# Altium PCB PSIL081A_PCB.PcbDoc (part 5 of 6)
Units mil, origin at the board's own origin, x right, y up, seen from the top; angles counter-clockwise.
Board outline 14000 x 8000 mil, 10 copper layers (Top Layer, Signal Layer 1, Signal Layer 2, Signal Layer 3, Signal Layer 4, Signal Layer 5, Signal Layer 6, Signal Layer 7, Signal Layer 8, Bottom Layer), stack 60.9 mil thick; 433 components, 510 nets, 1716 pads, 590 vias.
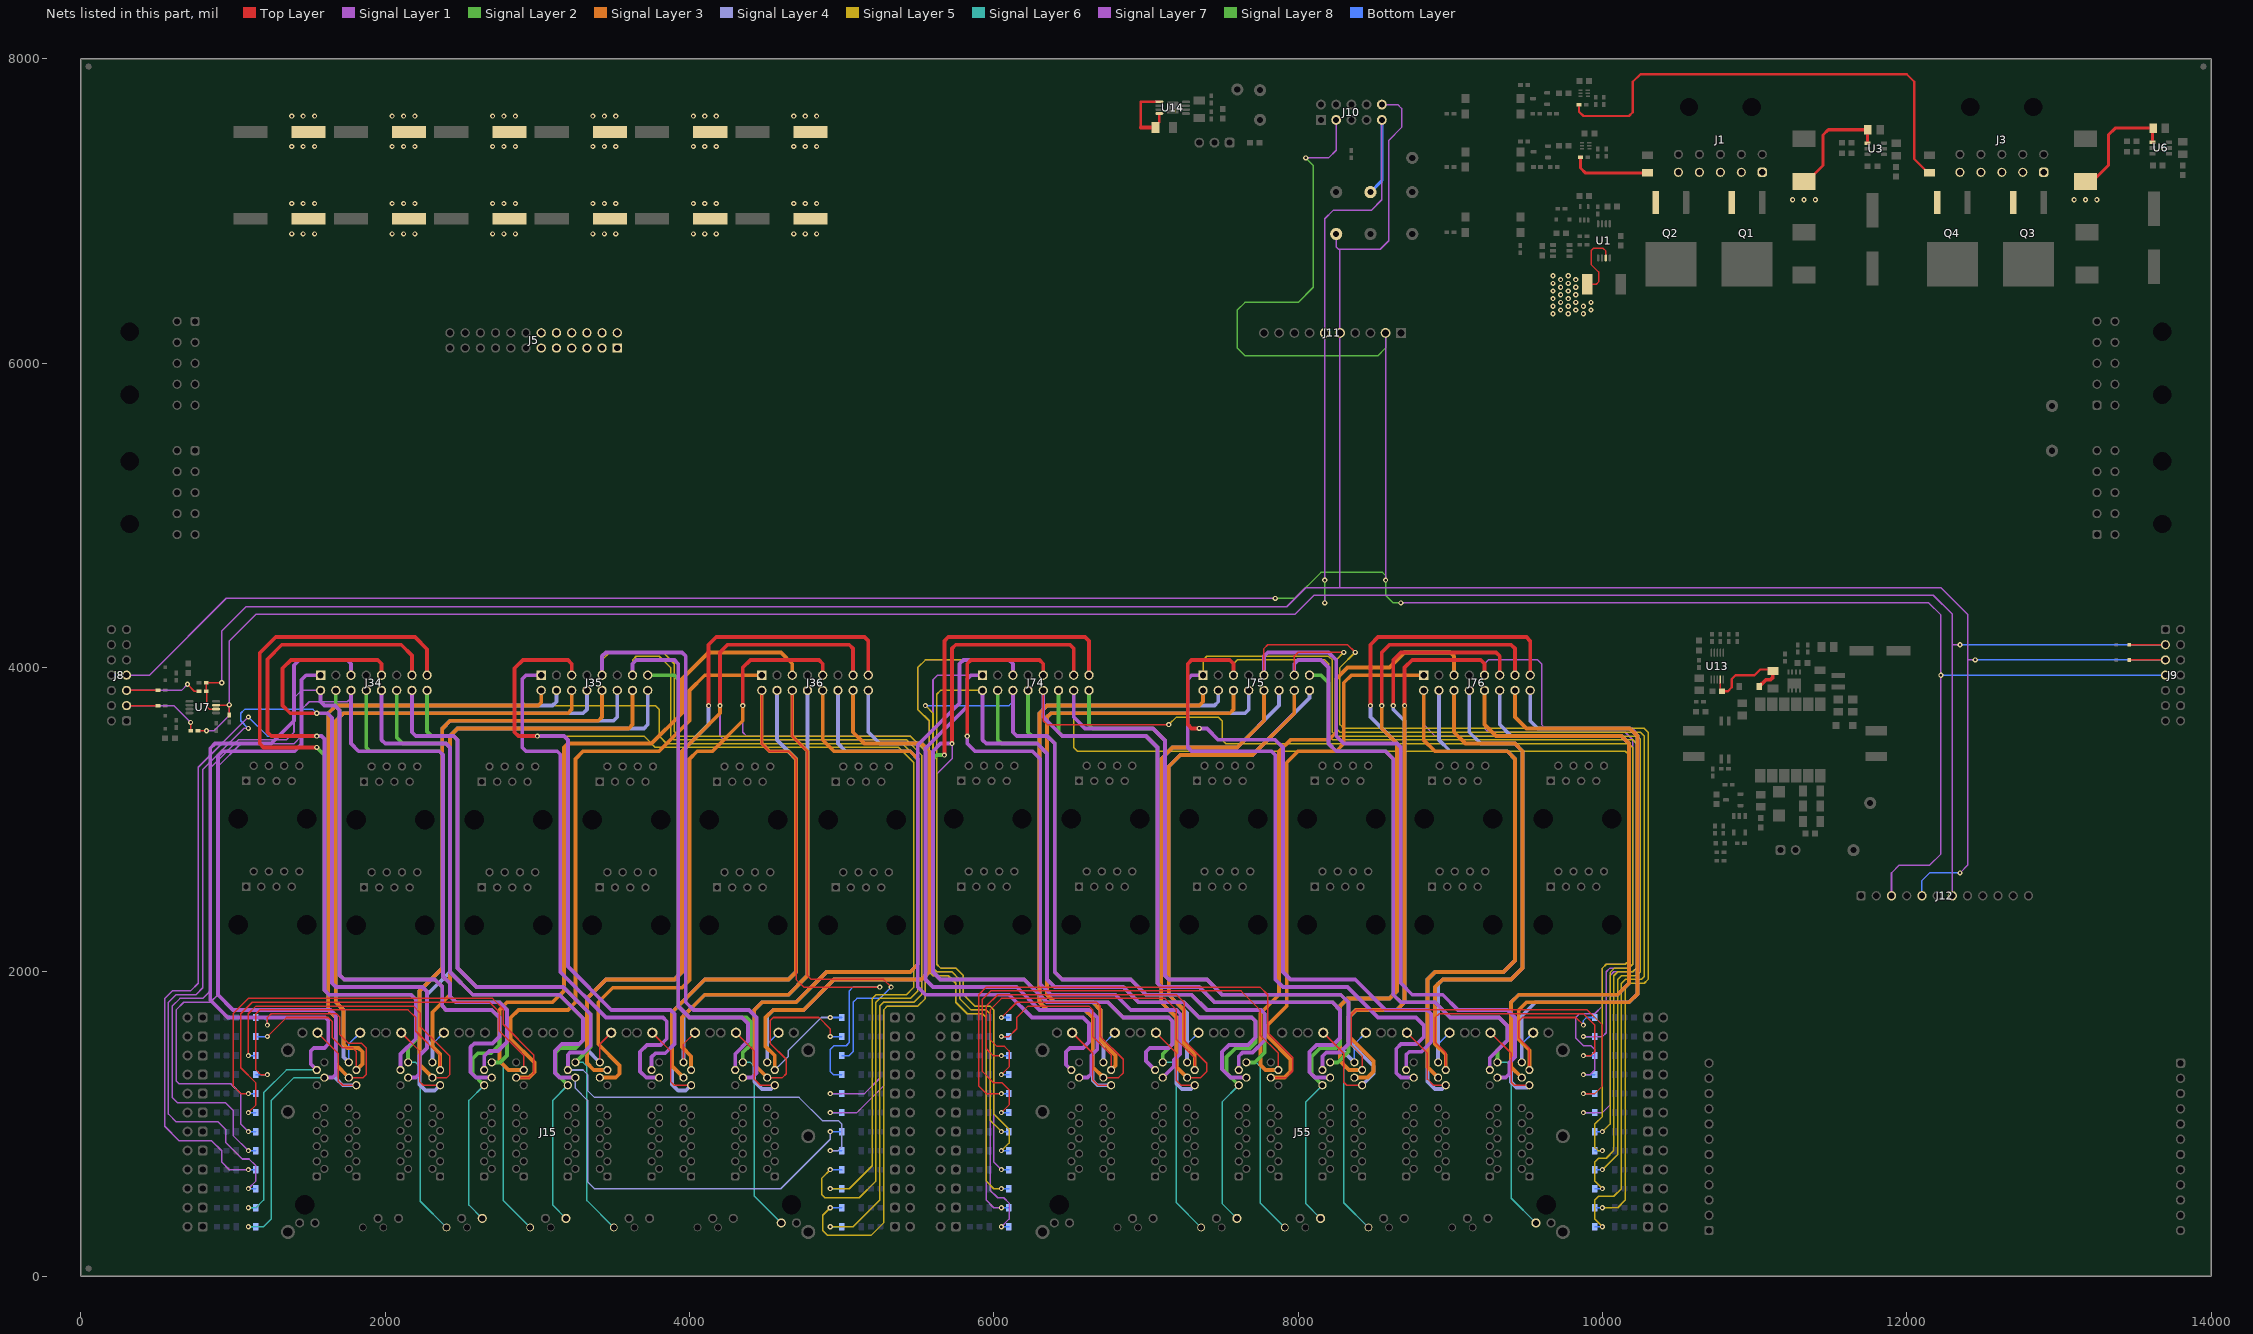
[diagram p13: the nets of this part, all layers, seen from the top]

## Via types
v1: diameter 34, hole 16, Top Layer to Bottom Layer, 429 vias
v2: diameter 26, hole 8, Top Layer to Bottom Layer, 156 vias
v3: diameter 19.68, hole 7.87, Top Layer to Bottom Layer, 5 vias

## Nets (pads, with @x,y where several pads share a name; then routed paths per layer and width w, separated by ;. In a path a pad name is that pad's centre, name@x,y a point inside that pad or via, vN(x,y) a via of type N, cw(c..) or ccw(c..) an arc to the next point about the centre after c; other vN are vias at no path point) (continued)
PSE_N3_F: J55.H11 J55.H16 J76.11 | length 4659.6
  Top Layer w10: J55.H16@8165.04,1599.84 8300,1464.88 8300,1275 8320,1255 8420.12,1255 J55.H11@8420.16,1254.96 ; J55.H11@8409.55,1244.35 8413.94,1239.96 8435.16,1239.96 J55.H11@8435.16,1269.96
  Top Layer w25: v1(8625,3750) 8625,4050 8675,4100 9300,4100 9325,4075 J76.11@9325,3950
  Signal Layer 4 w25: J55.H11@8420.16,1254.96 8495,1329.8 8495,1380 8330,1545 8330,1700 8380,1750 8650,1750 8700,1800 8700,3650 8625,3725 v1(8625,3750)
PSE_N4_A: J15.C14 J15.C17 J34.15 | length 6222.3
  Top Layer w25: v1(1550,3475) 1200,3475 1175,3500 1175,4095 1280,4200 2195,4200 2275,4120 J34.15@2275,3950
  Signal Layer 2 w25: v1(1550,3475) 1600,3425 1600,1880 1630,1850 2170,1850 2200,1820 2200,1550 2149.92,1499.92 J15.C14@2149.92,1404.96
  Signal Layer 6 w10: J15.C14@2149.92,1404.96 2199.96,1404.96 2200,1405 2230,1375 2230,492.21 J15.C17@2402.28,319.92
PSE_N4_B: J15.K14 J15.K17 J35.15 | length 4356.8
  Signal Layer 2 w25: J35.15@3725,3950 3900,3950 3925,3925 3925,1775 4000,1700 4375,1700 4400,1675 4400,1520 4349.92,1469.92 J15.K14@4349.92,1404.96
  Signal Layer 6 w10: J15.K14@4349.92,1404.96 4399.96,1404.96 4400,1405 4425,1380 4425,527.52 J15.K17@4602.68,349.84
PSE_N4_C: J15.H14 J15.H17 J36.15 | length 4907.4
  Top Layer w10: J15.H14@3410.16,1404.96 3410,1405.12 3410,1524.88 J15.H17@3484.96,1599.84
  Top Layer w25: v1(4125,3750) 4125,4150 4175,4200 5150,4200 5175,4175 J36.15@5175,3950
  Signal Layer 4 w25: J15.H14@3410.16,1404.96 3325,1490.12 3325,1825 3450,1950 3900,1950 3950,2000 3950,3450 4125,3625 v1(4125,3750)
PSE_N4_D: J55.C14 J55.C17 J74.15 | length 6665.4
  Top Layer w25: v1(5675,3425) 5675,4175 5700,4200 6600,4200 6625,4175 J74.15@6625,3950
  Signal Layer 2 w25: v1(5675,3425) 5625,3425 5600,3400 5600,2000 5650,1950 6200,1950 6350,1800 6750,1800 6850,1700 7150,1700 7175,1675 7175,1525 7109.92,1459.92 J55.C14@7109.92,1404.96
  Signal Layer 6 w10: J55.C14@7109.92,1404.96 7174.96,1404.96 7175,1405 7200,1380 7200,482.2 J55.C17@7362.28,319.92
PSE_N4_E: J55.K14 J55.K17 J75.15 | length 4862
  Signal Layer 2 w25: J75.15@8075,3950 8150,3950 8200,3900 8200,3500 8250,3450 8575,3450 8625,3400 8625,1850 8675,1800 8900,1800 9000,1700 9320,1700 9375,1645 9375,1550 9309.92,1484.92 J55.K14@9309.92,1404.96
  Signal Layer 6 w10: J55.K14@9309.92,1404.96 9309.96,1405 9375,1405 9400,1380 9400,512.52 J55.K17@9562.68,349.84
PSE_N4_F: J55.H14 J55.H17 J76.15 | length 4705.3
  Top Layer w25: v1(8475,3750) 8475,4150 8525,4200 9500,4200 9525,4175 J76.15@9525,3950
  Signal Layer 4 w25: J55.H14@8370.16,1404.96 8275,1500.12 8275,1775 8325,1825 8600,1825 8650,1875 8650,3500 8475,3675 v1(8475,3750)
  Bottom Layer w10: J55.H14@8370.16,1404.96 8370.16,1525.04 J55.H17@8444.96,1599.84
PSE_N5_A: J15.E11 J15.E16 J34.4 | length 4670.7
  Signal Layer 2 w25: J34.4@1675,3850 1675,3745 1700,3720 1700,1980 1730,1950 2325,1950 2375,1900 2375,1775 2400,1750 2700,1750 2750,1700 2750,1520 2695,1465 2610,1465 2575,1430 2575,1329.88 J15.E11@2649.92,1254.96
  Signal Layer 6 w10: J15.E16@2637.32,379.76 2550,467.09 2550,1155.04 J15.E11@2649.92,1254.96
PSE_N5_B: J15.B11 J15.B16 J35.4 | length 4683.9
  Top Layer w10: J15.B16@1555.04,1599.84 1690,1464.88 1690,1285 1720,1255 1810.12,1255 J15.B11@1810.16,1254.96
  Signal Layer 4 w25: J15.B11@1810.16,1254.96 1810.12,1255 1720,1255 1675,1300 1675,1700 1625,1750 1625,3700 1675,3750 3100,3750 3125,3775 J35.4@3125,3850
PSE_N5_C: J15.J11 J15.J16 J36.4 | length 3972.8
  Top Layer w10: J15.J16@3755.04,1599.84 3875,1479.88 3875,1280 3900,1255 4010.12,1255 J15.J11@4010.16,1254.96
  Signal Layer 4 w25: J15.J11@4010.16,1254.96 3975.2,1220 3925,1220 3885,1260 3885,1735 4100,1950 4650,1950 4700,2000 4700,3400 4575,3525 J36.4@4575,3850
PSE_N5_D: J55.E11 J55.E16 J74.4 | length 5204.7
  Signal Layer 2 w25: J74.4@6025,3850 6025,3525 6050,3500 6285,3500 6350,3435 6350,1950 6400,1900 6850,1900 6950,1800 7250,1800 7350,1700 7695,1700 7720,1675 7720,1535 7685,1500 7590,1500 7530,1440 7530,1334.88 J55.E11@7609.92,1254.96
  Signal Layer 6 w10: J55.E16@7597.32,379.76 7500,477.09 7500,1145.04 J55.E11@7609.92,1254.96
PSE_N5_E: J55.B11 J55.B16 J75.4 | length 4620.5
  Top Layer w10: J55.B16@6515.04,1599.84 6650,1464.88 6650,1290 6685,1255 6770.12,1255 J55.B11@6770.16,1254.96
  Signal Layer 4 w25: J55.B11@6770.16,1254.96 6770.12,1255 6680,1255 6650,1285 6650,1700 6600,1750 6350,1750 6300,1800 6300,3700 6350,3750 7450,3750 7475,3775 J75.4@7475,3850
PSE_N5_F: J55.J11 J55.J16 J76.4 | length 4147.2
  Top Layer w10: J55.J16@8715.04,1599.84 8850,1464.88 8850,1295 8890,1255 8970.12,1255 J55.J11@8970.16,1254.96
  Signal Layer 4 w25: J76.4@8925,3850 8925,3525 9000,3450 9375,3450 9425,3400 9425,2075 9350,2000 8900,2000 8850,1950 8850,1280 8900,1230 8945.2,1230 J55.J11@8970.16,1254.96
PSE_N6_A: J15.E14 J15.E17 J34.8 | length 4554.3
  Signal Layer 2 w25: J34.8@1875,3850 1875,3475 1900,3450 2355,3450 2380,3425 2380,1970 2425,1925 2425,1840 2465,1800 2750,1800 2800,1750 2800,1450 2754.96,1404.96 J15.E14@2699.92,1404.96
  Signal Layer 6 w10: J15.E14@2699.92,1404.96 2749.96,1404.96 2750,1405 2775,1380 2775,497.21 J15.E17@2952.28,319.92
PSE_N6_B: J15.B14 J15.B17 J35.8 | length 4312.2
  Signal Layer 4 w25: J15.B14@1760.16,1404.96 1725,1440.12 1725,1750 1675,1800 1675,3650 1725,3700 3300,3700 3325,3725 J35.8@3325,3850
  Bottom Layer w10: J15.B14@1760.16,1404.96 1760.16,1525.04 J15.B17@1834.96,1599.84
PSE_N6_C: J15.J14 J15.J17 J36.8 | length 3345
  Top Layer w10: J15.J14@3960.16,1404.96 3960.16,1525.04 J15.J17@4034.96,1599.84
  Signal Layer 4 w25: J15.J14@3950,1405 J15.J14@3960.16,1394.84 ; J15.J14@3960.16,1404.96 3960.16,1710.16 4100,1850 4650,1850 4775,1975 J36.8@4775,3850
PSE_N6_D: J55.E14 J55.E17 J74.8 | length 5104.7
  Signal Layer 2 w25: J74.8@6225,3850 6225,3575 6250,3550 6350,3550 6400,3500 6400,2000 6450,1950 6900,1950 7000,1850 7300,1850 7400,1750 7755,1750 7780,1725 7780,1470 7714.96,1404.96 J55.E14@7659.92,1404.96
  Signal Layer 6 w10: J55.E14@7659.92,1404.96 7724.96,1404.96 7725,1405 7750,1380 7750,482.2 J55.E17@7912.28,319.92
PSE_N6_E: J55.B14 J55.B17 J75.8 | length 4266.4
  Signal Layer 4 w25: J55.B14@6720.16,1404.96 6720.16,1529.84 6700,1550 6700,1750 6650,1800 6400,1800 6350,1850 6350,3675 6375,3700 7650,3700 7675,3725 J75.8@7675,3850
  Bottom Layer w10: J55.B14@6720.16,1404.96 6720.16,1525.04 J55.B17@6794.96,1599.84
PSE_N6_F: J55.J14 J55.J17 J76.8 | length 3451.1
  Signal Layer 4 w25: J55.J14@8920.16,1414.84 J55.J14@8920.16,1404.96 8920,1920 8950,1950 9400,1950 9475,2025 9475,3450 9425,3500 9200,3500 9125,3575 J76.8@9125,3850
  Bottom Layer w10: J55.J14@8920.16,1404.96 8920.16,1525.04 J55.J17@8994.96,1599.84
PSE_N7_A: J15.G11 J15.G16 J34.12 | length 4722.3
  Signal Layer 2 w25: J34.12@2075,3850 2075,3540 2115,3500 2400,3500 2425,3475 2425,2000 2575,1850 3145,1850 3300,1695 3300,1550 3250,1500 3150,1500 3120,1470 3120,1334.88 J15.G11@3199.92,1254.96
  Signal Layer 6 w10: J15.G16@3187.32,379.76 3100,467.09 3100,1155.04 J15.G11@3199.92,1254.96
PSE_N7_B: J15.D11 J15.D16 J35.12 | length 4439.5
  Top Layer w10: J15.D16@2105.04,1599.84 2225,1479.88 2225,1280 2250.04,1254.96 J15.D11@2360.16,1254.96 J15.D11@2360.16,1254.96
  Signal Layer 4 w25: J15.D11@2360.16,1254.96 2325.2,1220 2265,1220 2225,1260 2225,1875 2375,2025 2375,3600 2425,3650 3500,3650 3525,3675 J35.12@3525,3850
PSE_N7_C: J15.L11 J15.L16 J36.12 | length 4608.2
  Top Layer w10: J15.L16@4305.04,1599.84 4425,1479.88 4425,1295 4465,1255 4560.12,1255 J15.L11@4560.16,1254.96
  Signal Layer 4 w25: J15.L11@4560.16,1254.96 4535.2,1230 4475,1230 4425,1280 4425,1750 4475,1800 4700,1800 4900,2000 5450,2000 5500,2050 5500,3400 5450,3450 5025,3450 4975,3500 J36.12@4975,3850
PSE_N7_D: J55.G11 J55.G16 J74.12 | length 5412.1
  Signal Layer 2 w25: J74.12@6425,3850 6425,3575 6450,3550 7000,3550 7075,3475 7075,1925 7100,1900 7350,1900 7450,1800 8225,1800 8275,1750 8275,1525 8250,1500 8145,1500 8090,1445 8090,1324.88 J55.G11@8159.92,1254.96
  Signal Layer 6 w10: J55.G16@8147.32,379.76 8050,477.09 8050,1145.04 J55.G11@8159.92,1254.96
PSE_N7_E: J55.D11 J55.D16 J75.12 | length 3844.8
  Top Layer w10: J55.D16@7065.04,1599.84 7200,1464.88 7200,1285 7230,1255 7320.12,1255 J55.D11@7320.16,1254.96 J55.D11@7320.16,1254.96
  Signal Layer 4 w25: J55.D11@7320.16,1254.96 7295.2,1230 7235,1230 7200,1265 7200,1700 7100,1800 7100,3400 7175,3475 7600,3475 7875,3750 J75.12@7875,3850
PSE_N7_F: J55.L11 J55.L16 J76.12 | length 4703.6
  Top Layer w10: J55.L16@9265.04,1599.84 9400,1464.88 9400,1275 9420,1255 9520.12,1255 J55.L11@9520.16,1254.96
  Signal Layer 4 w25: J76.12@9325,3850 9325,3625 9400,3550 10125,3550 10175,3500 10175,1925 10100,1850 9450,1850 9400,1800 9400,1275 9435,1240 9505.2,1240 J55.L11@9520.16,1254.96
PSE_N8_A: J15.G14 J15.G17 J34.16 | length 4569.6
  Signal Layer 2 w25: J34.16@2275,3850 2275,3580 2305,3550 2450,3550 2475,3525 2475,2025 2600,1900 3170,1900 3350,1720 3350,1505.04 J15.G14@3249.92,1404.96
  Signal Layer 6 w10: J15.G14@3249.92,1404.96 3299.96,1404.96 3300,1405 3325,1380 3325,497.21 J15.G17@3502.28,319.92
PSE_N8_B: J15.D14 J15.D17 J35.16 | length 4003.7
  Signal Layer 4 w25: J15.D14@2310.16,1404.96 2310.16,1514.84 2275,1550 2275,1850 2425,2000 2425,3550 2475,3600 3700,3600 3725,3625 J35.16@3725,3850
  Bottom Layer w10: J15.D14@2310.16,1404.96 2310.16,1525.04 J15.D17@2384.96,1599.84
PSE_N8_C: J15.L14 J15.L17 J36.16 | length 3892.7
  Signal Layer 4 w25: J15.L14@4510.16,1404.96 4510.16,1710.16 4550,1750 4750,1750 4950,1950 5525,1950 5575,2000 5575,3450 5525,3500 5250,3500 5175,3575 J36.16@5175,3850
  Bottom Layer w10: J15.L14@4510.16,1404.96 4510.16,1525.04 J15.L17@4584.96,1599.84
PSE_N8_D: J55.G14 J55.G17 J74.16 | length 5292.8
  Signal Layer 2 w25: J74.16@6625,3850 6625,3625 6650,3600 7045,3600 7125,3520 7125,1975 7150,1950 7400,1950 7500,1850 8280,1850 8330,1800 8330,1475 8259.96,1404.96 J55.G14@8209.92,1404.96
  Signal Layer 6 w10: J55.G14@8209.92,1404.96 8274.96,1404.96 8275,1405 8300,1380 8300,482.2 J55.G17@8462.28,319.92
PSE_N8_E: J55.D14 J55.D17 J75.16 | length 3382.1
  Signal Layer 4 w25: J55.D14@7270.16,1404.96 7270.16,1729.84 7150,1850 7150,3350 7225,3425 7700,3425 8075,3800 J75.16@8075,3850
  Bottom Layer w10: J55.D14@7270.16,1404.96 7270.16,1525.04 J55.D17@7344.96,1599.84
PSE_N8_F: J55.L14 J55.L17 J76.16 | length 3992.5
  Signal Layer 4 w25: J55.L14@9470.16,1404.96 9470.16,1709.84 9470,1710 9560,1800 10175,1800 10230,1855 10230,3550 10180,3600 9575,3600 9525,3650 J76.16@9525,3850
  Bottom Layer w10: J55.L14@9470.16,1404.96 9470.16,1525.04 J55.L17@9544.96,1599.84
PSE_P1_A: D10.1 J15.A12 J34.1 | length 5429.5
  Signal Layer 1 w25: J34.1@1575,3950 1480,3950 1450,3920 1450,3495 1405,3450 930,3450 900,3420 900,1850 1000,1750 1640,1750 1675,1715 1675,1325 1654.96,1304.96 J15.A12@1599.92,1304.96
  Signal Layer 6 w10: v1(1100,325) 1200,325 1250,375 1250,1155 1400,1305 J15.A12@1599.92,1304.96 J15.A12@1599.92,1304.96
  Bottom Layer w10: v1(1100,325) D10.1@1148.94,325
PSE_P1_B: D12.1 J15.I12 J35.1 | length 10536.8
  Signal Layer 1 w25: J35.1@3025,3950 2925,3950 2900,3925 2900,3475 2925,3450 3130,3450 3150,3430 3150,2000 3450,1700 3825,1700 3850,1675 3850,1560 3810,1520 3720,1520 3675,1475 3675,1345 3715,1305 J15.I12@3799.92,1304.96 J15.I12@3799.92,1304.96
  Signal Layer 5 w10: J35.1@3025,3950 2925,3950 2900,3925 2900,3775 2925,3750 3775,3750 3800,3725 3800,3550 3850,3500 5400,3500 5500,3400 5500,1875 5450,1825 5250,1825 5225,1800 5225,625 5115,515 4890,515 4870,535 4870,645 v1(4925,700)
  Bottom Layer w10: v1(4925,700) D12.1@5000.53,700
PSE_P1_C: D17.1 J15.F12 J36.1 | length 7342.6
  Top Layer w10: v1(1100,1200) 1050,1200 1000,1250 1000,1725 1100,1825 2705,1825 2775,1755 2775,1655 2975,1455 2975,1335 2945,1305 2875.16,1305 2875.16,1289.96 2853.94,1289.96 J15.F12@2849.55,1294.35
  Signal Layer 3 w25: J15.F12@2860.16,1304.96 2944.96,1304.96 2980,1340 2980,1405 2825,1560 2825,1700 2875,1750 3200,1750 3250,1800 3250,3400 3300,3450 3800,3450 4000,3650 4000,3850 4100,3950 J36.1@4475,3950
  Bottom Layer w10: v1(1100,1200) D17.1@1148.94,1200
PSE_P1_D: D34.1 J55.A12 J74.1 | length 8260.1
  Signal Layer 1 w25: J74.1@5925,3950 5850,3950 5825,3925 5825,3745 5550,3470 5550,1950 5600,1900 6150,1900 6300,1750 6630,1750 6680,1700 6680,1490 6640,1450 6640,1330 6614.96,1304.96 J55.A12@6559.92,1304.96
  Signal Layer 7 w10: J74.1@5925,3950 5630,3950 5600,3920 5600,2025 5625,2000 5725,2000 5775,1950 5775,1825 5850,1750 5950,1750 5975,1725 5975,565 6025,515 6065,515 6100,480 6100,375 v1(6050,325)
  Bottom Layer w10: v1(6050,325) D34.1@6099.47,325
PSE_P1_E: D36.1 J55.I12 J75.1 | length 10839.7
  Signal Layer 1 w25: J75.1@7375,3950 7300,3950 7275,3925 7275,3475 7300,3450 7825,3450 7850,3425 7850,1950 7900,1900 8325,1900 8525,1700 8775,1700 8825,1650 8825,1570 8780,1525 8675,1525 8645,1495 8645,1335 8675,1305 J55.I12@8759.92,1304.96 J55.I12@8759.92,1304.96
  Signal Layer 5 w10: J75.1@7375,3950 7375,4050 7400,4075 8200,4075 8225,4050 8225,3575 8250,3550 10230,3550 10250,3530 10250,2000 10225,1975 10125,1975 10100,1950 10100,800 v1(10000,700)
  Bottom Layer w10: D36.1@9950.53,700 v1(10000,700)
PSE_P1_F: D41.1 J55.F12 J76.1 | length 7156.4
  Top Layer w10: v1(6050,1200) 5950,1200 5900,1250 5900,1850 5950,1900 7750,1900 7800,1850 7800,1600 7965,1435 7965,1349.8 7920.2,1305 J55.F12@7820.16,1304.96 J55.F12@7820.16,1304.96
  Signal Layer 3 w25: J55.F12@7820.16,1304.96 7909.96,1304.96 7950,1345 7950,1425 7800,1575 7800,1650 7925,1775 7925,3375 8000,3450 8250,3450 8300,3500 8300,3900 8350,3950 J76.1@8825,3950
  Bottom Layer w10: v1(6050,1200) D41.1@6099.47,1200
PSE_P2_A: D13.1 J15.A13 J34.5 | length 5667.3
  Signal Layer 1 w25: J15.A13@1549.92,1354.96 1510,1394.88 1510,1480 1530,1500 1600,1500 1625,1525 1625,1680 1605,1700 965,1700 850,1815 850,3470 880,3500 1250,3500 1400,3650 1400,4015 1435,4050 1750,4050 1775,4025 J34.5@1775,3950
  Signal Layer 6 w10: v1(1100,450) 1150,450 1200,500 1200,1205 1350,1355 J15.A13@1549.92,1354.96 J15.A13@1549.92,1354.96
  Bottom Layer w10: v1(1100,450) D13.1@1148.94,450
PSE_P2_B: D15.1 J15.I13 J35.5 | length 9903.8
  Top Layer w25: v1(3000,3550) 2875,3550 2850,3575 2850,3995 2905,4050 3200,4050 3225,4025 J35.5@3225,3950
  Signal Layer 1 w25: v1(3000,3550) 3175,3550 3200,3525 3200,2035 3485,1750 3875,1750 3900,1725 3900,1525 3840,1465 3775,1465 3750,1440 3750,1355.04 J15.I13@3749.92,1354.96
  Signal Layer 5 w10: v1(3000,3550) 3700,3550 3775,3475 5375,3475 5475,3375 5475,1900 5425,1850 5225,1850 5200,1825 5200,725 5050,575 v1(4925,575)
  Bottom Layer w10: v1(4925,575) D15.1@5000.53,575
PSE_P2_C: D20.1 J15.F13 J36.5 | length 7559
  Top Layer w10: v1(1100,1075) 1150,1125 1150,1270 1050,1370 1050,1725 1125,1800 2685,1800 2750,1735 2750,1610 2910.16,1449.84 J15.F13@2910.16,1354.96
  Signal Layer 3 w25: J15.F13@2910.16,1354.96 2910.12,1355 2810,1355 2750,1415 2750,1750 2800,1800 3100,1800 3175,1875 3175,3475 3200,3500 3750,3500 3950,3700 3950,3925 4125,4100 4600,4100 4675,4025 J36.5@4675,3950
  Bottom Layer w10: v1(1100,1075) D20.1@1148.94,1075
PSE_P2_D: D37.1 J55.A13 J74.5 | length 9045.3
  Signal Layer 1 w25: J74.5@6125,3950 6125,4025 6100,4050 5800,4050 5775,4025 5775,3765 5500,3490 5500,1900 5550,1850 6100,1850 6250,1700 6585,1700 6625,1660 6625,1540 6585,1500 6500,1500 6475,1475 6475,1389.88 J55.A13@6509.92,1354.96
  Signal Layer 7 w10: v1(6050,450) 6000,450 5950,500 5950,1700 5925,1725 5825,1725 5750,1800 5750,1925 5700,1975 5600,1975 5575,2000 5575,3650 5500,3725 5500,4000 5550,4050 6100,4050 6125,4025 J74.5@6125,3950
  Bottom Layer w10: v1(6050,450) D37.1@6099.47,450
PSE_P2_E: D39.1 J55.I13 J75.5 | length 10970.4
  Top Layer w25: v1(7350,3600) 7300,3600 7275,3625 7275,4025 7300,4050 7550,4050 7575,4025 J75.5@7575,3950
  Signal Layer 1 w25: v1(7350,3600) 7400,3600 7475,3525 7850,3525 7900,3475 7900,2000 7950,1950 8375,1950 8575,1750 8850,1750 8875,1725 8875,1540 8810,1475 8730,1475 8710,1455 8710,1355.04 J55.I13@8709.92,1354.96
  Signal Layer 5 w10: J75.5@7575,3950 7575,4025 7600,4050 8175,4050 8200,4025 8200,3550 8225,3525 10200,3525 10225,3500 10225,2025 10200,2000 10100,2000 10075,1975 10075,825 10025,775 9975,775 9950,750 9950,625 v1(10000,575)
  Bottom Layer w10: D39.1@9950.53,575 v1(10000,575)
PSE_P2_F: D44.1 J55.F13 J76.5 | length 7268.2
  Top Layer w10: v1(6050,1075) 6100,1125 6100,1225 6055,1270 6000,1270 5925,1345 5925,1820 5980,1875 7625,1875 7750,1750 7750,1585 7870.16,1464.84 J55.F13@7870.16,1354.96
  Signal Layer 3 w25: J55.F13@7870.16,1354.96 7870.12,1355 7785,1355 7752.5,1387.5 7752.5,1727.5 7875,1850 7875,3450 7950,3525 8200,3525 8250,3575 8250,3925 8325,4000 8600,4000 8700,4100 9000,4100 9025,4075 J76.5@9025,3950
  Bottom Layer w10: v1(6050,1075) D44.1@6099.47,1075
PSE_P3_A: D22.1 J15.C12 J34.9 | length 8873.1
  Top Layer w25: v1(1550,3700) 1375,3700 1325,3750 1325,3995 1380,4050 1950,4050 1975,4025 J34.9@1975,3950
  Signal Layer 1 w25: v1(1550,3700) 1620,3700 1650,3670 1650,1925 1675,1900 2245,1900 2275,1870 2275,1500 2225,1450 2225,1330 2199.96,1304.96 J15.C12@2149.92,1304.96
  Signal Layer 7 w10: v1(1100,575) 1150,625 1150,725 1105,770 1060,770 950,880 950,965 900,1015 625,1015 575,1065 575,1800 625,1850 755,1850 800,1895 800,3330 1070,3600 v1(1100,3600)
  Bottom Layer w10: v1(1100,575) D22.1@1148.94,575 ; v1(1100,3600) 1050,3650 1050,3700 1075,3725 1525,3725 v1(1550,3700)
PSE_P3_B: D24.1 J15.K12 J35.9 | length 10743.1
  Signal Layer 1 w25: J35.9@3425,3950 3425,4075 3450,4100 3950,4100 3975,4075 3975,1800 4025,1750 4390,1750 4440,1700 4440,1335 4409.96,1304.96 J15.K12@4349.92,1304.96
  Signal Layer 5 w10: J35.9@3425,3950 3425,4050 3475,4100 3825,4100 3900,4025 3900,3580 3930,3550 5450,3550 5550,3450 5550,1825 5500,1775 5300,1775 5275,1750 5275,350 5195,270 4905,270 4875,300 4875,400 v1(4925,450)
  Bottom Layer w10: v1(4925,450) D24.1@5000.53,450
PSE_P3_C: D29.1 J15.H12 J36.9 | length 8573.7
  Top Layer w25: v1(4350,3750) 4350,4000 4400,4050 4850,4050 4875,4025 J36.9@4875,3950
  Signal Layer 3 w25: J15.H12@3410.16,1304.96 3514.96,1304.96 3540,1330 3540,1385 3400,1525 3400,1800 3495,1895 3950,1895 4000,1945 4000,3400 4050,3450 4150,3450 4350,3650 v1(4350,3750)
  Signal Layer 7 w10: v1(4350,3750) 4350,3575 4375,3550 5450,3550 5550,3450 5550,1825 5500,1775 5300,1775 5275,1750 5275,1250 5100,1075 v1(4925,1075)
  Bottom Layer w10: v1(4925,1075) D29.1@5000.53,1075
PSE_P3_D: D46.1 J55.C12 J74.9 | length 9370.4
  Top Layer w25: v1(5825,3550) 5825,4025 5850,4050 6300,4050 6325,4025 J74.9@6325,3950
  Signal Layer 1 w25: v1(5825,3550) 5825,3500 5875,3450 6255,3450 6305,3400 6305,1920 6375,1850 6800,1850 6900,1750 7200,1750 7225,1725 7225,1460 7185,1420 7185,1380.04 J55.C12@7109.92,1304.96
  Signal Layer 5 w10: v1(6050,575) 6000,575 5950,625 5950,1700 5925,1725 5825,1725 5750,1800 5750,1925 5700,1975 5600,1975 5575,2000 5575,3650 5500,3725 5500,4000 5550,4050 6300,4050 6325,4025 J74.9@6325,3950
  Bottom Layer w10: v1(6050,575) D46.1@6099.47,575
PSE_P3_E: D48.1 J55.K12 J75.9 | length 11239.4
  Top Layer w10: J75.9@7775,3950 7775,4125 7800,4150 8325,4150 v1(8375,4100)
  Signal Layer 1 w25: J75.9@7775,3950 7775,4075 7800,4100 8200,4100 8250,4050 8250,3550 8300,3500 8650,3500 8675,3475 8675,1925 8750,1850 8950,1850 9050,1750 9375,1750 9425,1700 9425,1440 9390,1405 9390,1330 9364.96,1304.96 J55.K12@9309.92,1304.96
  Signal Layer 5 w10: v1(8375,4100) 8275,4000 8275,3625 8300,3600 10275,3600 10300,3575 10300,1950 10275,1925 10175,1925 10150,1900 10150,500 10100,450 v1(10000,450)
  Bottom Layer w10: D48.1@9950.53,450 v1(10000,450)
PSE_P3_F: D53.1 J55.H12 J76.9 | length 8194.8
  Top Layer w25: v1(8700,3750) 8700,4000 8750,4050 9200,4050 9225,4025 J76.9@9225,3950
  Signal Layer 3 w25: J55.H12@8370.16,1304.96 J55.H12@8370.16,1304.96 8455,1305 8495,1345 8495,1415 8330,1580 8330,1700 8380,1750 8650,1750 8700,1800 v1(8700,3750)
  Signal Layer 7 w10: J76.9@9225,3950 9225,4025 9250,4050 9575,4050 9600,4025 9600,3625 9625,3600 10200,3600 10230,3570 10230,2030 10200,2000 10075,2000 10050,1975 10050,1125 10000,1075 v1(9875,1075)
  Bottom Layer w10: v1(9875,1075) D53.1@9950.53,1075
PSE_P4_A: D25.1 J15.C13 J34.13 | length 9053.3
  Top Layer w25: v1(1550,3550) 1250,3550 1225,3575 1225,4055 1320,4150 2105,4150 2175,4080 J34.13@2175,3950
  Signal Layer 1 w25: v1(1550,3550) 1580,3550 1600,3530 1600,1880 1630,1850 2170,1850 2200,1820 2200,1560 2100,1460 2100,1355.04 J15.C13@2099.92,1354.96
  Signal Layer 7 w10: v1(1100,700) 975,700 925,750 925,823.54 858.54,890 645,890 550,985 550,1825 600,1875 720,1875 770,1925 770,3345 v1(1100,3675)
  Bottom Layer w10: v1(1100,700) D25.1@1148.94,700 ; v1(1100,3675) 1225,3550 v1(1550,3550)
PSE_P4_B: D27.1 J15.K13 J35.13 | length 9665.9
  Signal Layer 1 w25: J35.13@3625,3950 3625,4025 3650,4050 3900,4050 3925,4025 3925,1775 4000,1700 4345,1700 4385,1660 4385,1545 4299.92,1459.92 J15.K13@4299.92,1354.96
  Signal Layer 5 w10: J35.13@3625,3950 3625,4050 3650,4075 3800,4075 3875,4000 3875,3550 3900,3525 5425,3525 5525,3425 5525,1850 5475,1800 5275,1800 5250,1775 5250,500 5075,325 v1(4925,325)
  Bottom Layer w10: v1(4925,325) D27.1@5000.53,325
PSE_P4_C: D32.1 J15.H13 J36.13 | length 8935.7
  Top Layer w25: v1(4200,3750) 4200,4100 4250,4150 5050,4150 5075,4125 J36.13@5075,3950
  Signal Layer 3 w25: J15.H13@3460.16,1354.96 3460.12,1355 3370,1355 3325,1400 3325,1825 3450,1950 3900,1950 3950,2000 3950,3450 4200,3700 v1(4200,3750)
  Signal Layer 7 w10: v1(4200,3750) 4200,3550 4225,3525 5425,3525 5525,3425 5525,1850 5475,1800 5275,1800 5250,1775 5250,1300 5150,1200 v1(4925,1200)
  Bottom Layer w10: v1(4925,1200) D32.1@5000.53,1200
PSE_P4_D: D49.1 J55.C13 J74.13 | length 8600.7
  Top Layer w25: v1(5725,3500) 5725,4125 5750,4150 6500,4150 6525,4125 J74.13@6525,3950
  Signal Layer 1 w25: v1(5725,3500) 5650,3500 5600,3450 5600,2000 5650,1950 6200,1950 6350,1800 6750,1800 6850,1700 7150,1700 7175,1675 7175,1525 7150,1500 7025,1500 7000,1475 7000,1414.88 J55.C13@7059.92,1354.96
  Signal Layer 7 w10: v1(5725,3500) 5725,3400 5625,3300 5625,2050 5650,2025 5750,2025 5800,1975 5800,1850 5875,1775 5975,1775 6000,1750 6000,750 v1(6050,700)
  Bottom Layer w10: v1(6050,700) D49.1@6099.47,700
PSE_P4_E: D51.1 J55.K13 J75.13 | length 10596.8
  Top Layer w10: J75.13@7975,3950 7975,4075 8000,4100 v1(8300,4100)
  Signal Layer 1 w25: J75.13@7975,3950 7975,4025 8000,4050 8150,4050 8200,4000 8200,3500 8250,3450 8575,3450 8625,3400 8625,1850 8675,1800 8900,1800 9000,1700 9320,1700 9375,1645 9375,1550 9259.92,1434.92 J55.K13@9259.92,1354.96
  Signal Layer 5 w10: v1(8300,4100) 8250,4050 8250,3600 8275,3575 10250,3575 10275,3550 10275,1970 10255,1950 10150,1950 10125,1925 10125,575 10075,525 9975,525 9950,500 9950,375 v1(10000,325)
  Bottom Layer w10: D51.1@9950.53,325 v1(10000,325)
PSE_P4_F: D56.1 J55.H13 J76.13 | length 7013.4
  Top Layer w10: J55.H13@8420.16,1354.96 8420.16,1449.84 8350,1520 8350,1720 8380,1750 9900,1750 10000,1650 10000,1249.47 9950.53,1200 v1(9875,1200)
  Top Layer w25: v1(8550,3750) 8550,4100 8600,4150 9400,4150 9425,4125 J76.13@9425,3950
  Signal Layer 3 w25: J55.H13@8420.16,1354.96 8420.12,1355 8335,1355 8275,1415 8275,1775 8325,1825 8600,1825 8650,1875 8650,3500 8550,3600 v1(8550,3750)
  Bottom Layer w10: v1(9875,1200) D56.1@9950.53,1200
PSE_P5_A: D11.1 J15.E12 J34.2 | length 8080.5
  Signal Layer 1 w25: J34.2@1575,3850 1575,3775 1600,3750 1670,3750 1700,3720 1700,1980 1730,1950 2325,1950 2375,1900 2375,1775 2400,1750 2700,1750 2750,1700 2750,1575 2705,1530 2585,1530 2560,1505 2560,1340 2595,1305 J15.E12@2699.92,1304.96 J15.E12@2699.92,1304.96
  Signal Layer 7 w10: v1(1100,825) 1000,925 1000,1090 950,1140 635,1140 600,1175 600,1775 650,1825 800,1825 850,1875 850,3340 1035,3525 1350,3525 1400,3575 1400,3800 1450,3850 J34.2@1575,3850
  Bottom Layer w10: v1(1100,825) D11.1@1148.94,825
PSE_P5_B: D16.1 J15.B12 J35.2 | length 5240.5
  Top Layer w10: v1(1225,1650) 1225,1700 1250,1725 1680,1725 1700,1705 1700,1590 1760,1530 1845,1530 1875,1500 1875,1325 1854.96,1304.96 J15.B12@1760.16,1304.96
  Signal Layer 3 w25: J15.B12@1760.16,1304.96 1675,1390.12 1675,1700 1625,1750 1625,3700 1675,3750 3005,3750 3025,3770 J35.2@3025,3850
  Bottom Layer w10: D16.1@1148.94,1700 1200,1700 1225,1675 v1(1225,1650)
PSE_P5_C: D18.1 J15.J12 J36.2 | length 6962.3
  Top Layer w10: J36.2@4475,3850 4475,3500 4525,3450 4650,3450 4700,3400 4700,1950 4750,1900 v1(5250,1900)
  Signal Layer 3 w25: J15.J12@3960.16,1304.96 3885,1380.12 3885,1735 4100,1950 4650,1950 4700,2000 4700,3400 4650,3450 4525,3450 4475,3500 J36.2@4475,3850
  Bottom Layer w10: D18.1@5000.53,1325 4945,1325 4925,1345 4925,1490 4950,1515 5030,1515 5050,1535 5050,1875 5075,1900 v1(5250,1900)
PSE_P5_D: D35.1 J55.E12 J74.2 | length 8112.7
  Signal Layer 1 w25: J74.2@5925,3850 5925,3525 5950,3500 6285,3500 6350,3435 6350,1950 6400,1900 6850,1900 6950,1800 7250,1800 7350,1700 7695,1700 7720,1675 7720,1570 7670,1520 7545,1520 7500,1475 7500,1360 7555,1305 J55.E12@7659.92,1304.96 J55.E12@7659.92,1304.96
  Signal Layer 5 w10: J74.2@5925,3850 5650,3850 5625,3825 5625,2050 5650,2025 5750,2025 5800,1975 5800,1850 5875,1775 5975,1775 6000,1750 6000,1065 6100,965 6100,875 v1(6050,825)
  Bottom Layer w10: v1(6050,825) D35.1@6099.47,825
PSE_P5_E: D40.1 J55.B12 J75.2 | length 5292.2
  Top Layer w10: v1(6050,1700) 6150,1800 6675,1800 6700,1775 6700,1575 6850,1425 6850,1335 6819.96,1304.96 J55.B12@6720.16,1304.96
  Signal Layer 3 w25: J55.B12@6720.16,1304.96 6650,1375.12 6650,1700 6600,1750 6350,1750 6300,1800 6300,3700 6350,3750 7350,3750 7375,3775 J75.2@7375,3850
  Bottom Layer w10: v1(6050,1700) D40.1@6099.47,1700
PSE_P5_F: D42.1 J55.J12 J76.2 | length 7901.1
  Signal Layer 3 w25: J76.2@8825,3850 8825,3525 8900,3450 9375,3450 9425,3400 9425,2075 9350,2000 8900,2000 8850,1950 8850,1375.12 J55.J12@8920.16,1304.96
  Signal Layer 7 w10: J76.2@8825,3850 8825,3625 8900,3550 10135,3550 10175,3510 10175,2075 10150,2050 10025,2050 10000,2025 10000,1775 9950,1725 9850,1725 9825,1700 9825,1565 9875,1515 9925,1515 9950,1490 9950,1355 9920,1325 v1(9875,1325)
  Bottom Layer w10: v1(9875,1325) D42.1@9950.53,1325
PSE_P6_A: D14.1 J15.E13 J34.6 | length 7766.6
  Signal Layer 1 w25: J34.6@1775,3850 1775,3500 1825,3450 2355,3450 2380,3425 2380,1970 2425,1925 2425,1840 2465,1800 2750,1800 2800,1750 2800,1540 2740,1480 2685,1480 2649.92,1444.92 J15.E13@2649.92,1354.96
  Signal Layer 7 w10: v1(1100,950) 1050,1000 1050,1200 985,1265 645,1265 625,1285 625,1750 675,1800 850,1800 900,1850 900,3350 1050,3500 1400,3500 1450,3550 1450,3725 1500,3775 1750,3775 1775,3800 J34.6@1775,3850
  Bottom Layer w10: v1(1100,950) D14.1@1148.94,950
PSE_P6_B: D19.1 J15.B13 J35.6 | length 5121.7
  Top Layer w10: v1(1225,1575) 1350,1700 1625,1700 1650,1675 1650,1570 1720,1500 1785,1500 1810.16,1474.84 J15.B13@1810.16,1354.96
  Signal Layer 3 w25: J15.B13@1810.16,1354.96 1850,1394.8 1850,1475 1825,1500 1750,1500 1725,1525 1725,1750 1675,1800 1675,3650 1725,3700 3200,3700 3225,3725 J35.6@3225,3850
  Bottom Layer w10: D19.1@1148.94,1575 v1(1225,1575)
PSE_P6_C: D21.1 J15.J13 J36.6 | length 6424
  Top Layer w10: J36.6@4675,3850 4675,3550 4775,3450 4775,1975 4800,1950 5275,1950 v1(5325,1900)
  Signal Layer 3 w25: J15.J13@4010.16,1354.96 4010,1355.12 4010,1445 3950,1505 3950,1700 4100,1850 4650,1850 4775,1975 4775,3450 4675,3550 J36.6@4675,3850
  Bottom Layer w10: D21.1@5000.53,1450 5050,1450 5075,1475 5075,1800 5100,1825 5250,1825 v1(5325,1900)
PSE_P6_D: D38.1 J55.E13 J74.6 | length 7887.6
  Signal Layer 1 w25: J74.6@6125,3850 6125,3575 6150,3550 6350,3550 6400,3500 6400,2000 6450,1950 6900,1950 7000,1850 7300,1850 7400,1750 7755,1750 7780,1725 7780,1550 7700,1470 7635,1470 7610,1445 7610,1355.04 J55.E13@7609.92,1354.96
  Signal Layer 5 w10: v1(5550,3750) 5600,3700 5600,2025 5625,2000 5725,2000 5775,1950 5775,1825 5850,1750 5950,1750 5975,1725 5975,1025 v1(6050,950)
  Bottom Layer w10: v1(5550,3750) 6100,3750 6125,3775 J74.6@6125,3850 ; v1(6050,950) D38.1@6099.47,950
PSE_P6_E: D43.1 J55.B13 J75.6 | length 5267.1
  Top Layer w10: v1(6050,1575) 6099.47,1575 6150,1625.53 6150,1700 6225,1775 6625,1775 6650,1750 6650,1575 6770.16,1454.84 J55.B13@6770.16,1354.96
  Signal Layer 3 w25: J55.B13@6770.16,1354.96 6800,1384.8 6800,1450 6700,1550 6700,1750 6650,1800 6400,1800 6350,1850 6350,3675 6375,3700 7550,3700 7575,3725 J75.6@7575,3850
  Bottom Layer w10: v1(6050,1575) D43.1@6099.47,1575
PSE_P6_F: D45.1 J55.J13 J76.6 | length 5204.1
  Top Layer w10: J55.J13@8970.16,1354.96 8970.16,1469.84 8900,1540 8900,1700 8925,1725 9875,1725 9950,1650 9950,1475 9925,1450 v1(9875,1450)
  Signal Layer 3 w25: J55.J13@8970.16,1354.96 8970.16,1454.84 8900,1525 8900,1900 8950,1950 9400,1950 9475,2025 9475,3450 9425,3500 9100,3500 9025,3575 J76.6@9025,3850
  Bottom Layer w10: v1(9875,1450) D45.1@9950.53,1450
PSE_P7_A: D23.1 J15.G12 J34.10 | length 6515.3
  Signal Layer 1 w25: J34.10@1975,3850 1975,3525 2000,3500 2400,3500 2425,3475 2425,2000 2575,1850 3145,1850 3300,1695 3300,1550 3275,1525 3160,1525 3115,1480 3115,1335 3145,1305 J15.G12@3249.92,1304.96 J15.G12@3249.92,1304.96
  Signal Layer 4 w10: J15.G12@3249.92,1304.96 3249.92,1235.08 3330,1155 3330,620 3375,575 4600,575 4925,900 v1(4925,950)
  Bottom Layer w10: v1(4925,950) D23.1@5000.53,950
PSE_P7_B: D28.1 J15.D12 J35.10 | length 5750.7
  Top Layer w10: v1(1100,1450) 1100,1725 1150,1775 2185,1775 2230,1730 2230,1640 2425,1445 2425,1325 2404.96,1304.96 J15.D12@2310.16,1304.96
  Signal Layer 3 w25: J15.D12@2310.16,1304.96 2225,1390.12 2225,1875 2375,2025 2375,3600 2425,3650 3400,3650 3425,3675 J35.10@3425,3850
  Bottom Layer w10: v1(1100,1450) D28.1@1148.94,1450
PSE_P7_C: D30.1 J15.L12 J36.10 | length 5119.9
  Top Layer w10: J15.L12@4510.16,1304.96 4609.96,1304.96 4635,1330 4635,1425 4530,1530 4530,1680 4550,1700 4850,1700 4925,1625 v1(4925,1575)
  Signal Layer 3 w25: J15.L12@4510.16,1304.96 4425,1390.12 4425,1750 4475,1800 4700,1800 4900,2000 5450,2000 5500,2050 5500,3400 5450,3450 4950,3450 4875,3525 J36.10@4875,3850
  Bottom Layer w10: v1(4925,1575) D30.1@5000.53,1575
PSE_P7_D: D47.1 J55.G12 J74.10 | length 11512.1
  Top Layer w10: J74.10@6325,3850 6325,3650 6350,3625 v1(7150,3625)
  Signal Layer 1 w25: J74.10@6325,3850 6325,3675 6450,3550 7000,3550 7075,3475 7075,1925 7100,1900 7350,1900 7450,1800 8225,1800 8275,1750 8275,1565 8230,1520 8120,1520 8075,1475 8075,1340 8110,1305 J55.G12@8209.92,1304.96 J55.G12@8209.92,1304.96
  Signal Layer 5 w10: v1(7150,3625) 7200,3675 7475,3675 7500,3650 7500,3525 7525,3500 10175,3500 10200,3475 10200,2050 10175,2025 10080,2025 10050,1995 10050,1000 v1(10000,950)
  Bottom Layer w10: D47.1@9950.53,950 v1(10000,950)
PSE_P7_E: D52.1 J55.D12 J75.10 | length 5607.5
  Top Layer w10: v1(6050,1450) 5995,1450 5950,1495 5950,1775 6025,1850 7200,1850 7250,1800 7250,1550 7400,1400 7400,1345 7359.96,1304.96 J55.D12@7270.16,1304.96
  Signal Layer 3 w25: J55.D12@7270.16,1304.96 7200,1375.12 7200,1700 7100,1800 7100,3400 7175,3475 7600,3475 7775,3650 J75.10@7775,3850
  Bottom Layer w10: v1(6050,1450) D52.1@6099.47,1450
PSE_P7_F: D54.1 J55.L12 J76.10 | length 7715.3
  Signal Layer 3 w25: J76.10@9225,3850 9225,3625 9300,3550 10125,3550 10175,3500 10175,1925 10100,1850 9450,1850 9400,1800 9400,1375.12 J55.L12@9470.16,1304.96
  Signal Layer 7 w10: J76.10@9225,3850 9225,3600 9250,3575 10150,3575 10200,3525 10200,2050 10175,2025 10050,2025 10025,2000 10025,1600 10000,1575 v1(9875,1575)
  Bottom Layer w10: v1(9875,1575) D54.1@9950.53,1575
PSE_P8_A: D26.1 J15.G13 J34.14 | length 5896.5
  Signal Layer 1 w25: J34.14@2175,3850 2175,3575 2200,3550 2450,3550 2475,3525 2475,2025 2600,1900 3170,1900 3350,1720 3350,1515 3305,1470 3215,1470 3200,1455 3200,1355.04 J15.G13@3199.92,1354.96
  Signal Layer 4 w10: J15.G13@3199.92,1354.96 3299.96,1354.96 3300,1355 3330,1325 3330,1220 3375,1175 4720,1175 4875,1020 4980,1020 5000,1000 5000,850 4975,825 v1(4925,825)
  Bottom Layer w10: v1(4925,825) D26.1@5000.53,825
PSE_P8_B: D31.1 J15.D13 J35.14 | length 5745.4
  Top Layer w10: v1(1225,1325) 1180,1325 1150,1355 1150,1725 1175,1750 2150,1750 2200,1700 2200,1610 2360.16,1449.84 J15.D13@2360.16,1354.96
  Signal Layer 3 w25: J15.D13@2360.16,1354.96 2360.16,1459.84 2310,1510 2310,1735 2425,1850 2425,3550 2475,3600 3600,3600 3625,3625 J35.14@3625,3850
  Bottom Layer w10: D31.1@1148.94,1325 v1(1225,1325)
PSE_P8_C: D33.1 J15.L13 J36.14 | length 4452.8
  Signal Layer 3 w25: J15.L13@4560.16,1354.96 4560.16,1449.84 4500,1510 4500,1700 4550,1750 4750,1750 4950,1950 5525,1950 5575,2000 5575,3450 5525,3500 5150,3500 5075,3575 J36.14@5075,3850
  Signal Layer 4 w10: J15.L13@4560.16,1354.96 4650,1444.8 4650,1485 4865,1700 v1(4925,1700)
  Bottom Layer w10: v1(4925,1700) D33.1@5000.53,1700
PSE_P8_D: D50.1 J55.G13 J74.14 | length 11129.8
  Signal Layer 1 w25: J74.14@6525,3850 6525,3675 6600,3600 7045,3600 7125,3520 7125,1975 7150,1950 7400,1950 7500,1850 8280,1850 8330,1800 8330,1525 8275,1470 8185,1470 8160,1445 8160,1355.04 J55.G13@8159.92,1354.96
  Signal Layer 5 w10: J74.14@6525,3850 6525,3475 6550,3450 10150,3450 10175,3425 10175,2075 10150,2050 10025,2050 10000,2025 10000,1050 9950,1000 9950,845 9970,825 v1(10000,825)
  Bottom Layer w10: D50.1@9950.53,825 v1(10000,825)
PSE_P8_E: D55.1 J55.D13 J75.14 | length 5493.7
  Top Layer w10: v1(6050,1325) 6100,1375 6100,1480 6070,1510 6020,1510 5975,1555 5975,1750 6050,1825 7125,1825 7200,1750 7200,1555 7320.16,1434.84 J55.D13@7320.16,1354.96
  Signal Layer 3 w25: J55.D13@7320.16,1354.96 7320,1355.12 7320,1460 7250,1530 7250,1750 7150,1850 7150,3350 7225,3425 7700,3425 7975,3700 J75.14@7975,3850
  Bottom Layer w10: v1(6050,1325) D55.1@6099.47,1325
PSE_P8_F: D57.1 J55.L13 J76.14 | length 4893.3
  Top Layer w10: J55.L13@9520.16,1354.96 9520.16,1494.32 9450,1564.48 9450,1675 9475,1700 9825,1700 v1(9875,1650)
  Signal Layer 3 w25: J76.14@9425,3850 9425,3675 9500,3600 10180,3600 10230,3550 10230,1855 10175,1800 9500,1800 9450,1750 9450,1555 9520,1485 9520,1355.12 J55.L13@9520.16,1354.96
  Bottom Layer w10: v1(9875,1650) 9875,1680 9895,1700 D57.1@9950.53,1700
RESET: J8.7 J9.7 J10.3 J11.2 J12.3 | length 20813.5
  Signal Layer 7 w10: J8.7@300,3950 450,3950 955,4455 v1(7850,4455) ; v1(8050,7350) 8200,7350 8250,7400 J10.3@8250,7600 ; v1(8575,4575) J11.2@8575,6200 ; v1(8675,4425) 12145,4425 12225,4345 v1(12225,3950) 12225,2775 12150,2700 11950,2700 11900,2650 J12.3@11900,2500
  Signal Layer 8 w10: v1(7850,4455) 7980,4455 8150,4625 8555,4625 8575,4605 v1(8575,4575) 8575,4475 8625,4425 v1(8675,4425) ; v1(8050,7350) 8100,7300 8100,6500 8000,6400 7650,6400 7600,6350 7600,6100 7650,6050 8525,6050 8575,6100 J11.2@8575,6200
  Bottom Layer w10: v1(12225,3950) J9.7@13700,3950
SCL: D61.1 J9.3 J10.9 J11.6 J12.7 R12.2 R15.1 TP5.1 U7.7 | length 19913.1
  Top Layer w10: R15.1@768.62,3585 v1(825,3585) ; U7.7@887.6,3752.8 972.8,3752.8 v1(975,3755) R12.2@975,3688.62 ; D61.1@13463.31,4150 J9.3@13700,4150
  Signal Layer 7 w10: v1(825,3585) 875,3585 975,3685 v1(975,3755) 975,4175 1150,4350 7980,4350 8105,4475 8175,4475 ; v1(8175,4425) 8175,4475 ; v1(8175,4575) J11.6@8175,6200 8175,6950 8230,7005 8480,7005 8550,7075 J10.9@8550,7600 ; J12.7@12300,2500 12300,4150 ; v1(12350,4150) 12300,4150 ; 8175,4475 12175,4475 12300,4350 12300,4150
  Signal Layer 8 w10: v1(8175,4425) v1(8175,4575)
  Bottom Layer w10: v1(12350,4150) J9.3@13700,4150
  Bottom Layer w20: TP5.1@8475,7125 8550,7200 J10.9@8550,7600
SCLA: J8.3 R15.2 R16.1 | length 727.5
  Top Layer w10: J8.3@300,3750 R16.1@506.38,3750 ; v1(720,3640) 720,3586.38 R15.2@721.38,3585
  Signal Layer 7 w10: J8.3@300,3750 610,3750 v1(720,3640)
SDA: D60.1 J9.5 J10.10 J11.5 J12.5 R13.2 R14.1 TP4.1 U7.6 | length 19690.1
  Top Layer w10: U7.6@887.6,3727.2 842.8,3727.2 825,3745 825,3843.62 R14.1@823.62,3845 R13.2@823.62,3900 v1(925,3900) ; D60.1@13463.31,4050 J9.5@13700,4050
  Signal Layer 7 w10: v1(925,3900) 925,4240 1085,4400 7925,4400 8050,4525 8275,4525 ; TP4.1@8250,6850 8250,6765 8265,6750 8540,6750 8595,6805 8595,7465 8680,7550 8680,7675 8655,7700 J10.10@8550,7700 ; 8275,6750 J11.5@8275,6200 8275,4525 ; v1(12350,2650) 12400,2700 12400,4050 ; v1(12450,4050) 12400,4050 ; 8275,4525 12225,4525 12400,4350 12400,4050
  Bottom Layer w10: J12.5@12100,2500 12100,2600 12150,2650 v1(12350,2650) ; v1(12450,4050) J9.5@13700,4050
SDAA: J8.5 R14.2 R17.1 | length 718
  Top Layer w10: J8.5@300,3850 R17.1@506.38,3850 ; v1(700,3890) 745,3845 R14.2@776.38,3845
  Signal Layer 7 w10: J8.5@300,3850 660,3850 v1(700,3890)
VCC: C40.2 C42.2 D8.1 U13.4 | length 674.1
  Top Layer w10: U13.4@10774.68,3922.4 10774.68,3856.81 C40.2@10786.5,3845
  Top Layer w15: C40.2@10786.5,3845 10825,3845 10850,3870 10850,3925 10875,3950 11000,3950 11036.93,3986.93 C42.2@11120,3986.93
  Top Layer w25: D8.1@11029.47,3875 11030,3875 11075,3920 11105,3920 11120,3935 C42.2@11120,3986.93
VIN1: C3.2 C56.1 D2.1 J1.1 J1.2 J1.3 J1.4 J1.5 Q1.3 Q2.3 R25.1 U3.4 | length 1294.3
  Top Layer w20: R25.1@9856.38,7355 9856.38,7283.62 9890,7250 10288.07,7250 C3.2@10295,7243.07 ; D2.1@11325,7194.51 11344.51,7194.51 11450,7300 11450,7500 11485,7535 C56.1@11745,7535 11740.86,7530.86 U3.4@11740.86,7447.4
  other v1: 11250,7075 11325,7075 11400,7075
VIN2: C9.2 C57.1 D5.1 J3.1 J3.2 J3.3 J3.4 J3.5 Q3.3 Q4.3 R26.1 U6.4 | length 3953.6
  Top Layer w15: R26.1@9846.38,7700 9846.38,7653.62 9875,7625 10175,7625 10200,7650 10200,7850 10250,7900 12000,7900 12050,7850 12050,7343.07 C9.2@12150,7243.07
  Top Layer w20: D5.1@13185,7194.51 13219.51,7194.51 13325,7300 13325,7500 13370,7545 C57.1@13620,7545 13615.87,7540.87 U6.4@13615.87,7452.4
  other v1: 13100,7075 13175,7075 13250,7075
VPWR: C11.1 C12.1 C13.1 C14.1 C15.1 C16.1 C17.1 C18.1 C19.1 C20.1 C21.1 C22.1 C46.1 J5.1 J5.2 J5.3 J5.4 J5.5 J5.6 J5.7 J5.8 J5.9 J5.10 J5.11 J5.12 R4.1 U1.3 U14.5 U14.8 | length 942.1
  Top Layer w10: R4.1@9907.64,6520 9960,6520 9975,6535 9975,6600 9925,6650 9925,6740 9940,6755 10005,6755 10022.8,6737.2 U1.3@10022.8,6692.8
  Top Layer w15: 6965,7550 6965,7720 6966.61,7718.39 U14.5@7087.4,7718.39 ; C46.1@7053.07,7550 7087.4,7584.33 U14.8@7087.4,7641.61
  Top Layer w25: 6965,7550 C46.1@7053.07,7550
  other v1: 9675,6325 9775,6325 9875,6325 9725,6350 9825,6350 9925,6350 9675,6375 9775,6375 9875,6375 9725,6400 9825,6400 9925,6400 9675,6425 9775,6425 9725,6450 9825,6450 9675,6475 9775,6475 9725,6500 9825,6500 9675,6525 9775,6525 9725,6550 9825,6550 9675,6575 9775,6575 1385,6850 1460,6850 1535,6850 2045,6850 2120,6850 2195,6850 2705,6850 2780,6850 2855,6850 3365,6850 3440,6850 3515,6850 4025,6850 4100,6850 4175,6850 4685,6850 4760,6850 4835,6850 1385,7050 1460,7050 1535,7050 2045,7050 2120,7050 2195,7050 2705,7050 2780,7050 2855,7050 3365,7050 3440,7050 3515,7050 4025,7050 4100,7050 4175,7050 4685,7050 4760,7050 4835,7050 1385,7425 1460,7425 1535,7425 2045,7425 2120,7425 2195,7425 2705,7425 2780,7425 2855,7425 3365,7425 3440,7425 3515,7425 4025,7425 4100,7425 4175,7425 4685,7425 4760,7425 4835,7425 1385,7625 1460,7625 1535,7625 2045,7625 2120,7625 2195,7625 2705,7625 2780,7625 2855,7625 3365,7625 3440,7625 3515,7625 4025,7625 4100,7625 4175,7625 4685,7625 4760,7625 4835,7625
pads on no net: FID1.1 FID2.1 FID3.1 FID4.1 FID5.1 FID6.1 J1.ALIGN1 J1.ALIGN2 J2.ALIGN1 J2.ALIGN2 J3.ALIGN1 J3.ALIGN2 J4.ALIGN1 J4.ALIGN2 J6.ALIGN1 J6.ALIGN2 J7.ALIGN1 J7.ALIGN2 J8.4 J8.6 J8.8 J8.10 J8.12 J9.4 J9.6 J9.8 J9.10 J9.12 J10.2 J10.4 J10.8 J11.8 J12.11 J15.A9 J15.B9 J15.C9 J15.D9 J15.E9 J15.F9 J15.G9 J15.H9 J15.I9 J15.J9 J15.K9 J15.L9 J15.MH1 J15.MH2 J16.MH1 J16.MH2 J18.MH1 J18.MH2 J20.MH1 J20.MH2 J25.MH1 J25.MH2 J27.MH1 J27.MH2 J29.MH1 J29.MH2 J37.MH1 J37.MH2 J39.MH1 J39.MH2 J41.MH1 J41.MH2 J46.MH1 J46.MH2 J48.MH1 J48.MH2 J50.MH1 J50.MH2 J55.A9 J55.B9 J55.C9 J55.D9 J55.E9 J55.F9 J55.G9 J55.H9 J55.I9 J55.J9 J55.K9 J55.L9 J55.MH1 J55.MH2 J56.MH1 J56.MH2 J58.MH1 J58.MH2 J60.MH1 J60.MH2 J65.MH1 J65.MH2 J67.MH1 J67.MH2 J69.MH1 J69.MH2 J77.MH1 J77.MH2 J79.MH1 J79.MH2 J81.MH1 J81.MH2 J86.MH1 J86.MH2 J88.MH1 J88.MH2 J90.MH1 J90.MH2 J95.1 J95.2 J95.3 J95.4 J95.5 J95.6 J95.7 J95.8 J95.9 J95.10 J95.11 J95.12 J96.1 J96.2 J96.3 J96.4 J96.5 J96.6 J96.7 J96.8 J96.9 J96.10 J96.11 J96.12 SH-J1.0 SH-J2.0 SH-J3.0 SH-J4.0 SH-J5.0 SH-J6.0 SH-J7.0 SH-J8.0 SH-J9.0 SH-J10.0 SH-J11.0 SH-J12.0 SH-J13.0 SH-J14.0 SH-J15.0 SH-J16.0 SH-J17.0 SH-J18.0 SH-J19.0 SH-J20.0 SH-J21.0 SH-J22.0 SH-J23.0 SH-J24.0 SH-J25.0 SH-J26.0 SH-J27.0 SH-J28.0 SH-J29.0 SH-J30.0 SH-J31.0 SH-J32.0 SH-J33.0 SH-J34.0 SH-J35.0 SH-J36.0 SH-J37.0 SH-J38.0 SH-J39.0 SH-J40.0 SH-J41.0 SH-J42.0 SH-J43.0 SH-J44.0 SH-J45.0 SH-J46.0 SH-J47.0 SH-J48.0 SH-J49.0 SH-J50.0 T1.2 T1.4 U1.1 U3.3 U6.3 U8.1 U8.2 U14.3 U14.6 U14.7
